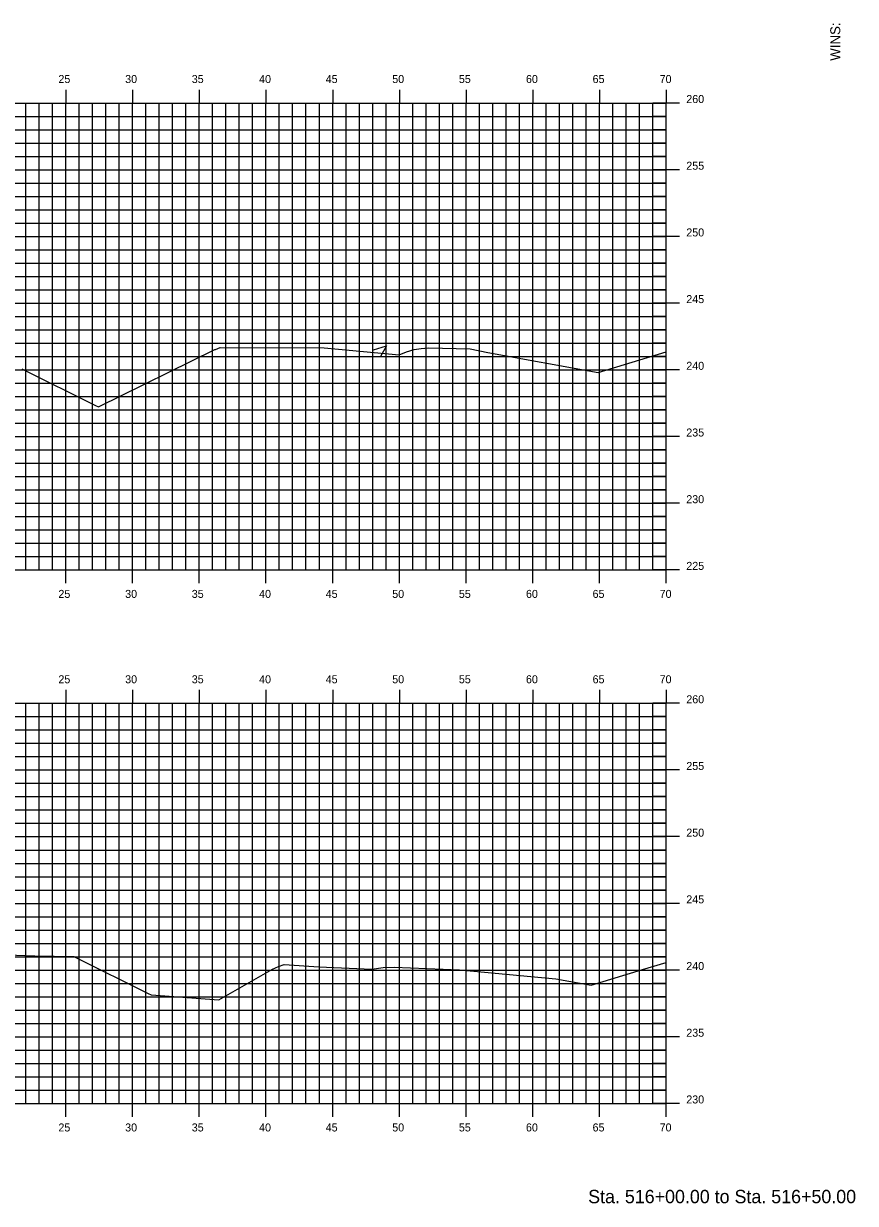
# Model space of a CAD drawing. Extents: x 1170543 to 1177585, y 609599 to 610623.
# Drawn here: x 1173752.9 to 1173815.2, y 610270.3 to 610358.8 of the extents above; entities that cross this region are included whole.
import ezdxf

# ---------------------------------------------------------------- set-up
doc = ezdxf.new("R2010")
doc.units = 0
for name, color, linetype in [('BORDER', 7, 'Continuous'), ('D_Utilities_UG_Water_Shutoff', 7, 'Continuous'), ('H_V ANNOTATION', 7, 'Continuous'), ('MAJOR', 7, 'Continuous'), ('MINOR', 7, 'Continuous'), ('S_Roadway_Centerline', 7, 'Continuous')]:
    doc.layers.add(name, color=color, linetype=linetype)

msp = doc.modelspace()

# ---------------------------------------------------------------- linework, layer by layer
at = {"layer": 'D_Utilities_UG_Water_Shutoff'}
msp.add_lwpolyline([(1173779.113, 610334.301), (1173780.093, 610334.606), (1173779.639, 610333.802)], dxfattribs=at)
at = {"layer": 'MAJOR'}
for p, q in [((1173756.063, 610353.803), (1173756.063, 610352.801)), ((1173761.063, 610353.803), (1173761.063, 610352.801)), ((1173766.063, 610353.803), (1173766.063, 610352.801)), ((1173771.063, 610353.803), (1173771.063, 610352.801)), ((1173776.063, 610353.803), (1173776.063, 610352.801)), ((1173781.063, 610353.803), (1173781.063, 610352.801)), ((1173786.063, 610353.803), (1173786.063, 610352.801)), ((1173791.063, 610353.803), (1173791.063, 610352.801)), ((1173796.063, 610353.803), (1173796.063, 610352.801)), ((1173801.063, 610353.803), (1173801.063, 610352.801)), ((1173661.063, 610352.801), (1173801.063, 610352.801)), ((1173661.063, 610352.801), (1173801.063, 610352.801)), ((1173756.063, 610317.801), (1173756.063, 610352.801)), ((1173761.063, 610317.801), (1173761.063, 610352.801)), ((1173766.063, 610317.801), (1173766.063, 610352.801)), ((1173771.063, 610317.801), (1173771.063, 610352.801)), ((1173776.063, 610317.801), (1173776.063, 610352.801)), ((1173781.063, 610317.801), (1173781.063, 610352.801)), ((1173786.063, 610317.801), (1173786.063, 610352.801)), ((1173791.063, 610317.801), (1173791.063, 610352.801)), ((1173796.063, 610317.801), (1173796.063, 610352.801)), ((1173802.065, 610352.801), (1173800.061, 610352.801)), ((1173801.063, 610317.801), (1173801.063, 610352.801)), ((1173801.063, 610317.801), (1173801.063, 610352.801)), ((1173661.063, 610347.801), (1173801.063, 610347.801)), ((1173802.065, 610347.801), (1173800.061, 610347.801)), ((1173661.063, 610342.801), (1173801.063, 610342.801)), ((1173802.065, 610342.801), (1173800.061, 610342.801)), ((1173661.063, 610337.801), (1173801.063, 610337.801)), ((1173802.065, 610337.801), (1173800.061, 610337.801)), ((1173661.063, 610332.801), (1173801.063, 610332.801)), ((1173802.065, 610332.801), (1173800.061, 610332.801)), ((1173661.063, 610327.801), (1173801.063, 610327.801)), ((1173802.065, 610327.801), (1173800.061, 610327.801)), ((1173661.063, 610322.801), (1173801.063, 610322.801)), ((1173802.065, 610322.801), (1173800.061, 610322.801)), ((1173661.063, 610317.801), (1173801.063, 610317.801)), ((1173661.063, 610317.801), (1173801.063, 610317.801)), ((1173756.063, 610316.799), (1173756.063, 610317.801)), ((1173761.063, 610316.799), (1173761.063, 610317.801)), ((1173766.063, 610316.799), (1173766.063, 610317.801)), ((1173771.063, 610316.799), (1173771.063, 610317.801)), ((1173776.063, 610316.799), (1173776.063, 610317.801)), ((1173781.063, 610316.799), (1173781.063, 610317.801)), ((1173786.063, 610316.799), (1173786.063, 610317.801)), ((1173791.063, 610316.799), (1173791.063, 610317.801)), ((1173796.063, 610316.799), (1173796.063, 610317.801)), ((1173802.065, 610317.801), (1173800.061, 610317.801)), ((1173801.063, 610316.799), (1173801.063, 610317.801)), ((1173756.063, 610308.803), (1173756.063, 610307.801)), ((1173761.063, 610308.803), (1173761.063, 610307.801)), ((1173766.063, 610308.803), (1173766.063, 610307.801)), ((1173771.063, 610308.803), (1173771.063, 610307.801)), ((1173776.063, 610308.803), (1173776.063, 610307.801)), ((1173781.063, 610308.803), (1173781.063, 610307.801)), ((1173786.063, 610308.803), (1173786.063, 610307.801)), ((1173791.063, 610308.803), (1173791.063, 610307.801)), ((1173796.063, 610308.803), (1173796.063, 610307.801)), ((1173801.063, 610308.803), (1173801.063, 610307.801)), ((1173661.063, 610307.801), (1173801.063, 610307.801)), ((1173661.063, 610307.801), (1173801.063, 610307.801)), ((1173756.063, 610277.801), (1173756.063, 610307.801)), ((1173761.063, 610277.801), (1173761.063, 610307.801)), ((1173766.063, 610277.801), (1173766.063, 610307.801)), ((1173771.063, 610277.801), (1173771.063, 610307.801)), ((1173776.063, 610277.801), (1173776.063, 610307.801)), ((1173781.063, 610277.801), (1173781.063, 610307.801)), ((1173786.063, 610277.801), (1173786.063, 610307.801)), ((1173791.063, 610277.801), (1173791.063, 610307.801)), ((1173796.063, 610277.801), (1173796.063, 610307.801)), ((1173802.065, 610307.801), (1173800.061, 610307.801)), ((1173801.063, 610277.801), (1173801.063, 610307.801)), ((1173801.063, 610277.801), (1173801.063, 610307.801)), ((1173661.063, 610302.801), (1173801.063, 610302.801)), ((1173802.065, 610302.801), (1173800.061, 610302.801)), ((1173661.063, 610297.801), (1173801.063, 610297.801)), ((1173802.065, 610297.801), (1173800.061, 610297.801)), ((1173661.063, 610292.801), (1173801.063, 610292.801)), ((1173802.065, 610292.801), (1173800.061, 610292.801)), ((1173661.063, 610287.801), (1173801.063, 610287.801)), ((1173802.065, 610287.801), (1173800.061, 610287.801)), ((1173661.063, 610282.801), (1173801.063, 610282.801)), ((1173802.065, 610282.801), (1173800.061, 610282.801)), ((1173661.063, 610277.801), (1173801.063, 610277.801)), ((1173661.063, 610277.801), (1173801.063, 610277.801)), ((1173756.063, 610276.799), (1173756.063, 610277.801)), ((1173761.063, 610276.799), (1173761.063, 610277.801)), ((1173766.063, 610276.799), (1173766.063, 610277.801)), ((1173771.063, 610276.799), (1173771.063, 610277.801)), ((1173776.063, 610276.799), (1173776.063, 610277.801)), ((1173781.063, 610276.799), (1173781.063, 610277.801)), ((1173786.063, 610276.799), (1173786.063, 610277.801)), ((1173791.063, 610276.799), (1173791.063, 610277.801)), ((1173796.063, 610276.799), (1173796.063, 610277.801)), ((1173802.065, 610277.801), (1173800.061, 610277.801)), ((1173801.063, 610276.799), (1173801.063, 610277.801))]:
    msp.add_line(p, q, dxfattribs=at)
at = {"layer": 'MINOR'}
for p, q in [((1173753.063, 610317.801), (1173753.063, 610352.801)), ((1173754.063, 610317.801), (1173754.063, 610352.801)), ((1173755.063, 610317.801), (1173755.063, 610352.801)), ((1173757.063, 610317.801), (1173757.063, 610352.801)), ((1173758.063, 610317.801), (1173758.063, 610352.801)), ((1173759.063, 610317.801), (1173759.063, 610352.801)), ((1173760.063, 610317.801), (1173760.063, 610352.801)), ((1173762.063, 610317.801), (1173762.063, 610352.801)), ((1173763.063, 610317.801), (1173763.063, 610352.801)), ((1173764.063, 610317.801), (1173764.063, 610352.801)), ((1173765.063, 610317.801), (1173765.063, 610352.801)), ((1173767.063, 610317.801), (1173767.063, 610352.801)), ((1173768.063, 610317.801), (1173768.063, 610352.801)), ((1173769.063, 610317.801), (1173769.063, 610352.801)), ((1173770.063, 610317.801), (1173770.063, 610352.801)), ((1173772.063, 610317.801), (1173772.063, 610352.801)), ((1173773.063, 610317.801), (1173773.063, 610352.801)), ((1173774.063, 610317.801), (1173774.063, 610352.801)), ((1173775.063, 610317.801), (1173775.063, 610352.801)), ((1173777.063, 610317.801), (1173777.063, 610352.801)), ((1173778.063, 610317.801), (1173778.063, 610352.801)), ((1173779.063, 610317.801), (1173779.063, 610352.801)), ((1173780.063, 610317.801), (1173780.063, 610352.801)), ((1173782.063, 610317.801), (1173782.063, 610352.801)), ((1173783.063, 610317.801), (1173783.063, 610352.801)), ((1173784.063, 610317.801), (1173784.063, 610352.801)), ((1173785.063, 610317.801), (1173785.063, 610352.801)), ((1173787.063, 610317.801), (1173787.063, 610352.801)), ((1173788.063, 610317.801), (1173788.063, 610352.801)), ((1173789.063, 610317.801), (1173789.063, 610352.801)), ((1173790.063, 610317.801), (1173790.063, 610352.801)), ((1173792.063, 610317.801), (1173792.063, 610352.801)), ((1173793.063, 610317.801), (1173793.063, 610352.801)), ((1173794.063, 610317.801), (1173794.063, 610352.801)), ((1173795.063, 610317.801), (1173795.063, 610352.801)), ((1173797.063, 610317.801), (1173797.063, 610352.801)), ((1173798.063, 610317.801), (1173798.063, 610352.801)), ((1173799.063, 610317.801), (1173799.063, 610352.801)), ((1173800.063, 610317.801), (1173800.063, 610352.801)), ((1173661.063, 610351.801), (1173801.063, 610351.801)), ((1173801.063, 610351.801), (1173800.061, 610351.801)), ((1173661.063, 610350.801), (1173801.063, 610350.801)), ((1173801.063, 610350.801), (1173800.061, 610350.801)), ((1173661.063, 610349.801), (1173801.063, 610349.801)), ((1173801.063, 610349.801), (1173800.061, 610349.801)), ((1173661.063, 610348.801), (1173801.063, 610348.801)), ((1173801.063, 610348.801), (1173800.061, 610348.801)), ((1173661.063, 610346.801), (1173801.063, 610346.801)), ((1173801.063, 610346.801), (1173800.061, 610346.801)), ((1173661.063, 610345.801), (1173801.063, 610345.801)), ((1173801.063, 610345.801), (1173800.061, 610345.801)), ((1173661.063, 610344.801), (1173801.063, 610344.801)), ((1173801.063, 610344.801), (1173800.061, 610344.801)), ((1173661.063, 610343.801), (1173801.063, 610343.801)), ((1173801.063, 610343.801), (1173800.061, 610343.801)), ((1173661.063, 610341.801), (1173801.063, 610341.801)), ((1173801.063, 610341.801), (1173800.061, 610341.801)), ((1173661.063, 610340.801), (1173801.063, 610340.801)), ((1173801.063, 610340.801), (1173800.061, 610340.801)), ((1173661.063, 610339.801), (1173801.063, 610339.801)), ((1173801.063, 610339.801), (1173800.061, 610339.801)), ((1173661.063, 610338.801), (1173801.063, 610338.801)), ((1173801.063, 610338.801), (1173800.061, 610338.801)), ((1173661.063, 610336.801), (1173801.063, 610336.801)), ((1173801.063, 610336.801), (1173800.061, 610336.801)), ((1173661.063, 610335.801), (1173801.063, 610335.801)), ((1173801.063, 610335.801), (1173800.061, 610335.801)), ((1173661.063, 610334.801), (1173801.063, 610334.801)), ((1173801.063, 610334.801), (1173800.061, 610334.801)), ((1173661.063, 610333.801), (1173801.063, 610333.801)), ((1173801.063, 610333.801), (1173800.061, 610333.801)), ((1173661.063, 610331.801), (1173801.063, 610331.801)), ((1173801.063, 610331.801), (1173800.061, 610331.801)), ((1173661.063, 610330.801), (1173801.063, 610330.801)), ((1173801.063, 610330.801), (1173800.061, 610330.801)), ((1173661.063, 610329.801), (1173801.063, 610329.801)), ((1173801.063, 610329.801), (1173800.061, 610329.801)), ((1173661.063, 610328.801), (1173801.063, 610328.801)), ((1173801.063, 610328.801), (1173800.061, 610328.801)), ((1173661.063, 610326.801), (1173801.063, 610326.801)), ((1173801.063, 610326.801), (1173800.061, 610326.801)), ((1173661.063, 610325.801), (1173801.063, 610325.801)), ((1173801.063, 610325.801), (1173800.061, 610325.801)), ((1173661.063, 610324.801), (1173801.063, 610324.801)), ((1173801.063, 610324.801), (1173800.061, 610324.801)), ((1173661.063, 610323.801), (1173801.063, 610323.801)), ((1173801.063, 610323.801), (1173800.061, 610323.801)), ((1173661.063, 610321.801), (1173801.063, 610321.801)), ((1173801.063, 610321.801), (1173800.061, 610321.801)), ((1173661.063, 610320.801), (1173801.063, 610320.801)), ((1173801.063, 610320.801), (1173800.061, 610320.801)), ((1173661.063, 610319.801), (1173801.063, 610319.801)), ((1173801.063, 610319.801), (1173800.061, 610319.801)), ((1173661.063, 610318.801), (1173801.063, 610318.801)), ((1173801.063, 610318.801), (1173800.061, 610318.801)), ((1173753.063, 610277.801), (1173753.063, 610307.801)), ((1173754.063, 610277.801), (1173754.063, 610307.801)), ((1173755.063, 610277.801), (1173755.063, 610307.801)), ((1173757.063, 610277.801), (1173757.063, 610307.801)), ((1173758.063, 610277.801), (1173758.063, 610307.801)), ((1173759.063, 610277.801), (1173759.063, 610307.801)), ((1173760.063, 610277.801), (1173760.063, 610307.801)), ((1173762.063, 610277.801), (1173762.063, 610307.801)), ((1173763.063, 610277.801), (1173763.063, 610307.801)), ((1173764.063, 610277.801), (1173764.063, 610307.801)), ((1173765.063, 610277.801), (1173765.063, 610307.801)), ((1173767.063, 610277.801), (1173767.063, 610307.801)), ((1173768.063, 610277.801), (1173768.063, 610307.801)), ((1173769.063, 610277.801), (1173769.063, 610307.801)), ((1173770.063, 610277.801), (1173770.063, 610307.801)), ((1173772.063, 610277.801), (1173772.063, 610307.801)), ((1173773.063, 610277.801), (1173773.063, 610307.801)), ((1173774.063, 610277.801), (1173774.063, 610307.801)), ((1173775.063, 610277.801), (1173775.063, 610307.801)), ((1173777.063, 610277.801), (1173777.063, 610307.801)), ((1173778.063, 610277.801), (1173778.063, 610307.801)), ((1173779.063, 610277.801), (1173779.063, 610307.801)), ((1173780.063, 610277.801), (1173780.063, 610307.801)), ((1173782.063, 610277.801), (1173782.063, 610307.801)), ((1173783.063, 610277.801), (1173783.063, 610307.801)), ((1173784.063, 610277.801), (1173784.063, 610307.801)), ((1173785.063, 610277.801), (1173785.063, 610307.801)), ((1173787.063, 610277.801), (1173787.063, 610307.801)), ((1173788.063, 610277.801), (1173788.063, 610307.801)), ((1173789.063, 610277.801), (1173789.063, 610307.801)), ((1173790.063, 610277.801), (1173790.063, 610307.801)), ((1173792.063, 610277.801), (1173792.063, 610307.801)), ((1173793.063, 610277.801), (1173793.063, 610307.801)), ((1173794.063, 610277.801), (1173794.063, 610307.801)), ((1173795.063, 610277.801), (1173795.063, 610307.801)), ((1173797.063, 610277.801), (1173797.063, 610307.801)), ((1173798.063, 610277.801), (1173798.063, 610307.801)), ((1173799.063, 610277.801), (1173799.063, 610307.801)), ((1173800.063, 610277.801), (1173800.063, 610307.801)), ((1173661.063, 610306.801), (1173801.063, 610306.801)), ((1173801.063, 610306.801), (1173800.061, 610306.801)), ((1173661.063, 610305.801), (1173801.063, 610305.801)), ((1173801.063, 610305.801), (1173800.061, 610305.801)), ((1173661.063, 610304.801), (1173801.063, 610304.801)), ((1173801.063, 610304.801), (1173800.061, 610304.801)), ((1173661.063, 610303.801), (1173801.063, 610303.801)), ((1173801.063, 610303.801), (1173800.061, 610303.801)), ((1173661.063, 610301.801), (1173801.063, 610301.801)), ((1173801.063, 610301.801), (1173800.061, 610301.801)), ((1173661.063, 610300.801), (1173801.063, 610300.801)), ((1173801.063, 610300.801), (1173800.061, 610300.801)), ((1173661.063, 610299.801), (1173801.063, 610299.801)), ((1173801.063, 610299.801), (1173800.061, 610299.801)), ((1173661.063, 610298.801), (1173801.063, 610298.801)), ((1173801.063, 610298.801), (1173800.061, 610298.801)), ((1173661.063, 610296.801), (1173801.063, 610296.801)), ((1173801.063, 610296.801), (1173800.061, 610296.801)), ((1173661.063, 610295.801), (1173801.063, 610295.801)), ((1173801.063, 610295.801), (1173800.061, 610295.801)), ((1173661.063, 610294.801), (1173801.063, 610294.801)), ((1173801.063, 610294.801), (1173800.061, 610294.801)), ((1173661.063, 610293.801), (1173801.063, 610293.801)), ((1173801.063, 610293.801), (1173800.061, 610293.801)), ((1173661.063, 610291.801), (1173801.063, 610291.801)), ((1173801.063, 610291.801), (1173800.061, 610291.801)), ((1173661.063, 610290.801), (1173801.063, 610290.801)), ((1173801.063, 610290.801), (1173800.061, 610290.801)), ((1173661.063, 610289.801), (1173801.063, 610289.801)), ((1173801.063, 610289.801), (1173800.061, 610289.801)), ((1173661.063, 610288.801), (1173801.063, 610288.801)), ((1173801.063, 610288.801), (1173800.061, 610288.801)), ((1173661.063, 610286.801), (1173801.063, 610286.801)), ((1173801.063, 610286.801), (1173800.061, 610286.801)), ((1173661.063, 610285.801), (1173801.063, 610285.801)), ((1173801.063, 610285.801), (1173800.061, 610285.801)), ((1173661.063, 610284.801), (1173801.063, 610284.801)), ((1173801.063, 610284.801), (1173800.061, 610284.801)), ((1173661.063, 610283.801), (1173801.063, 610283.801)), ((1173801.063, 610283.801), (1173800.061, 610283.801)), ((1173661.063, 610281.801), (1173801.063, 610281.801)), ((1173801.063, 610281.801), (1173800.061, 610281.801)), ((1173661.063, 610280.801), (1173801.063, 610280.801)), ((1173801.063, 610280.801), (1173800.061, 610280.801)), ((1173661.063, 610279.801), (1173801.063, 610279.801)), ((1173801.063, 610279.801), (1173800.061, 610279.801)), ((1173661.063, 610278.801), (1173801.063, 610278.801)), ((1173801.063, 610278.801), (1173800.061, 610278.801))]:
    msp.add_line(p, q, dxfattribs=at)
at = {"layer": 'S_Roadway_Centerline'}
for points in [[(1173752.76, 610332.882), (1173758.282, 610330.134), (1173758.513, 610330.019), (1173767.223, 610334.317), (1173767.231, 610334.314), (1173767.278, 610334.313), (1173767.625, 610334.484), (1173775.435, 610334.453), (1173781.04, 610333.93), (1173781.606, 610334.157), (1173782.16, 610334.316), (1173782.702, 610334.41), (1173783.232, 610334.44), (1173786.36, 610334.364), (1173787.685, 610334.088), (1173795.949, 610332.595), (1173801.063, 610334.139)], [(1173737.655, 610289.485), (1173753.638, 610288.874), (1173753.751, 610288.872), (1173756.654, 610288.819), (1173756.815, 610288.739), (1173762.24, 610286.05), (1173762.46, 610285.941), (1173767.535, 610285.559), (1173771.558, 610287.855), (1173772.002, 610288.076), (1173772.436, 610288.226), (1173775.028, 610288.052), (1173779.007, 610287.872), (1173779.838, 610288.002), (1173780.661, 610288.023), (1173785.576, 610287.823), (1173792.789, 610287.15), (1173795.426, 610286.673), (1173799.272, 610287.833), (1173801.063, 610288.357)]]:
    msp.add_lwpolyline(points, dxfattribs=at)

# ---------------------------------------------------------------- texts
at = {"layer": 'BORDER'}
msp.add_text('WINS:', height=0.7453, rotation=90, dxfattribs=at).set_placement((1173814.098, 610355.969))
at = {"layer": 'H_V ANNOTATION'}
for s, height, p in [('25', 0.6, (1173755.509, 610354.301)), ('30', 0.6, (1173760.512, 610354.301)), ('35', 0.6, (1173765.503, 610354.301)), ('40', 0.6, (1173770.549, 610354.301)), ('45', 0.6, (1173775.541, 610354.301)), ('50', 0.6, (1173780.527, 610354.301)), ('55', 0.6, (1173785.519, 610354.301)), ('60', 0.6, (1173790.549, 610354.301)), ('65', 0.6, (1173795.541, 610354.301)), ('70', 0.6, (1173800.565, 610354.301)), ('260', 0.6, (1173802.563, 610352.801)), ('255', 0.6, (1173802.563, 610347.801)), ('250', 0.6, (1173802.563, 610342.801)), ('245', 0.6, (1173802.563, 610337.801)), ('240', 0.6, (1173802.563, 610332.801)), ('235', 0.6, (1173802.563, 610327.801)), ('230', 0.6, (1173802.563, 610322.801)), ('225', 0.6, (1173802.563, 610317.801)), ('25', 0.6, (1173755.509, 610315.701)), ('30', 0.6, (1173760.512, 610315.701)), ('35', 0.6, (1173765.503, 610315.701)), ('40', 0.6, (1173770.549, 610315.701)), ('45', 0.6, (1173775.541, 610315.701)), ('50', 0.6, (1173780.527, 610315.701)), ('55', 0.6, (1173785.519, 610315.701)), ('60', 0.6, (1173790.549, 610315.701)), ('65', 0.6, (1173795.541, 610315.701)), ('70', 0.6, (1173800.565, 610315.701)), ('25', 0.6, (1173755.509, 610309.301)), ('30', 0.6, (1173760.512, 610309.301)), ('35', 0.6, (1173765.503, 610309.301)), ('40', 0.6, (1173770.549, 610309.301)), ('45', 0.6, (1173775.541, 610309.301)), ('50', 0.6, (1173780.527, 610309.301)), ('55', 0.6, (1173785.519, 610309.301)), ('60', 0.6, (1173790.549, 610309.301)), ('65', 0.6, (1173795.541, 610309.301)), ('70', 0.6, (1173800.565, 610309.301)), ('260', 0.6, (1173802.563, 610307.801)), ('255', 0.6, (1173802.563, 610302.801)), ('250', 0.6, (1173802.563, 610297.801)), ('245', 0.6, (1173802.563, 610292.801)), ('240', 0.6, (1173802.563, 610287.801)), ('235', 0.6, (1173802.563, 610282.801)), ('230', 0.6, (1173802.563, 610277.801)), ('25', 0.6, (1173755.509, 610275.701)), ('30', 0.6, (1173760.512, 610275.701)), ('35', 0.6, (1173765.503, 610275.701)), ('40', 0.6, (1173770.549, 610275.701)), ('45', 0.6, (1173775.541, 610275.701)), ('50', 0.6, (1173780.527, 610275.701)), ('55', 0.6, (1173785.519, 610275.701)), ('60', 0.6, (1173790.549, 610275.701)), ('65', 0.6, (1173795.541, 610275.701)), ('70', 0.6, (1173800.565, 610275.701)), ('Sta. 516+00.00 to Sta. 516+50.00', 1.0002, (1173795.209, 610270.321))]:
    msp.add_text(s, height=height, dxfattribs=at).set_placement(p)

doc.saveas('drawing.dxf')
